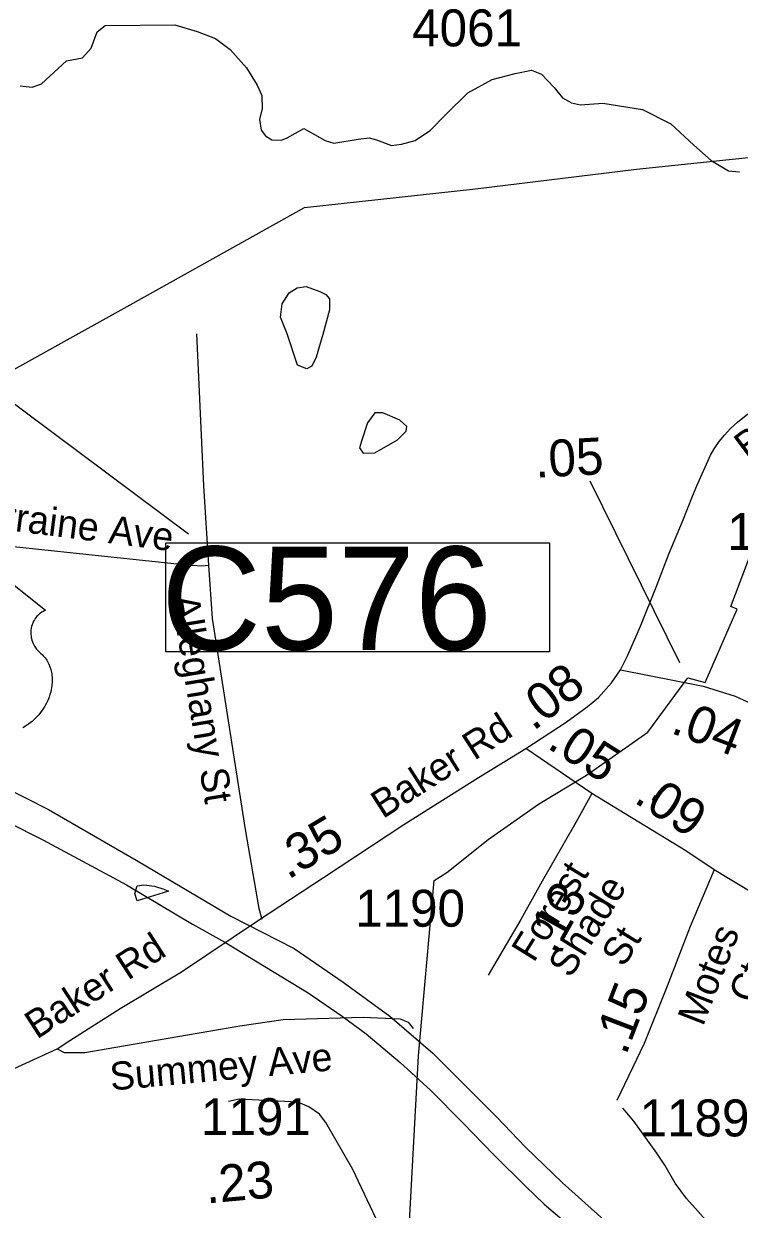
# Model space of a CAD drawing. Extents: x 1662474 to 1856135, y 779280 to 917889.
# Drawn here: x 1714222 to 1716644, y 797474 to 801486 of the extents above; entities that cross this region are included whole.
import ezdxf

# ---------------------------------------------------------------- set-up
doc = ezdxf.new("R2010")
doc.units = 0
for name, color, linetype in [('Exist Boundary Political City Limit New', 7, 'Continuous'), ('Exist Hydrographic Creek Single Shore', 7, 'Continuous'), ('Exist Hydrographic Misc Water Feature', 7, 'Continuous'), ('Exist Hydrographic Pond Under 1500 Sq Ft', 7, 'Continuous'), ('Exist Road Non-System Type 51', 7, 'Continuous'), ('Exist Road Non-System Type 51 Label', 7, 'Continuous'), ('Exist Road Primary Interstate Structure Culvert Number Label', 7, 'Continuous'), ('Exist Road Primary US Divided Attributed', 7, 'Continuous'), ('Exist Road Primary US Shield CELL', 7, 'Continuous'), ('Exist Road Secondary Mileage Hundredths English Label', 7, 'Continuous'), ('Exist Road Secondary Mileage Tenths English Label', 7, 'Continuous'), ('Exist Road Secondary Type 41 Attributed', 7, 'Continuous'), ('Exist Road Secondary Type 51 Attributed', 7, 'Continuous'), ('Exist Road Secondary Type 51 Label', 7, 'Continuous'), ('Exist Road Secondary Type 51 Number Label', 7, 'Continuous'), ('Exist Utilities Electrical Transmission Line', 7, 'Continuous'), ('Map Preparation Boundary City Limit Buffer Line', 7, 'Continuous'), ('Prop Road Primary US Projected', 7, 'Continuous')]:
    doc.layers.add(name, color=color, linetype=linetype)

msp = doc.modelspace()

# ---------------------------------------------------------------- linework, layer by layer
at = {"layer": 'Exist Boundary Political City Limit New'}
msp.add_lwpolyline([(1715477.8, 796498.7), (1715559, 797993.3), (1715611.1, 798586.8), (1715654.6, 798614.2), (1715793.8, 798724.9), (1715964.4, 798844.9), (1716127.2, 798943.5), (1716334.5, 799088.1), (1716469.9, 799272.8), (1716528.6, 799256.2), (1716637.1, 799505.2), (1716615.4, 799514.4), (1716691.5, 799713.8)], dxfattribs=at)
at = {"layer": 'Exist Hydrographic Creek Single Shore'}
msp.add_lwpolyline([(1714210.5, 801276.6), (1714251.1, 801271.9), (1714282.6, 801282.4), (1714367.4, 801361.1), (1714421.8, 801371.1), (1714451.1, 801403.1), (1714471.4, 801459), (1714498.4, 801480.5), (1714734.1, 801482.6), (1714809.4, 801460.1), (1714871.4, 801436.2), (1714921, 801398.9), (1714975.9, 801336.9), (1715012, 801278.2), (1715028.6, 801243.2), (1715029.6, 801199.4), (1715020.1, 801162.4), (1715026.5, 801126.4), (1715040.6, 801106.5), (1715061.6, 801093.1), (1715094.8, 801092.1), (1715114.4, 801100.5), (1715170, 801131.2), (1715242.5, 801091), (1715272.4, 801081.8), (1715353.8, 801095.5), (1715391.2, 801100.2), (1715416.8, 801093.1), (1715467.6, 801073.7), (1715500.8, 801078.7), (1715547.2, 801091), (1715598.9, 801126.2), (1715650.6, 801178.9), (1715725.1, 801252.4), (1715807.9, 801297.6), (1715886, 801318.3), (1715940.9, 801329.6), (1715975.2, 801315.2), (1716017.5, 801270), (1716046.4, 801235.9), (1716076, 801219.1), (1716107.2, 801212), (1716181.9, 801217), (1716316.2, 801195.5), (1716413, 801147.2), (1716490.5, 801074.8), (1716549.5, 801023.8), (1716607.2, 800988.7), (1716644.5, 800984.8)], dxfattribs=at)
at = {"layer": 'Exist Hydrographic Misc Water Feature'}
for points in [[(1714606, 798518.2), (1714598.4, 798542.2), (1714606.6, 798568.2), (1714628.6, 798572), (1714664.6, 798567.6), (1714696.5, 798557.3), (1714712.5, 798551.1), (1714694.3, 798545.3), (1714606, 798518.2)], [(1715933.2, 796479), (1715907.8, 796543.3), (1715884.4, 796615.5), (1715871.2, 796687.6), (1715859.8, 796757.8), (1715852.5, 796823.8), (1715847.1, 796887.9), (1715825.5, 796938.2), (1715789.8, 796974.4), (1715716.6, 797057.2), (1715671.2, 797123.6), (1715629.7, 797178.1), (1715582.2, 797224.5), (1715524.6, 797269.1), (1715487, 797317.4), (1715443.6, 797381.9), (1715365, 797546.6), (1715335.7, 797609), (1715245.2, 797767.8), (1715223.5, 797796.1), (1715187.7, 797820.5), (1715149.8, 797836.8), (1714951.9, 797846.7), (1714915.8, 797839)], [(1716675.7, 796508), (1716680.6, 796599.9), (1716687.6, 796709.9), (1716698.5, 796801.8), (1716709.9, 796949.7), (1716710.5, 797005.8), (1716709.3, 797087.8), (1716703.6, 797133.9), (1716682.3, 797208.2), (1716658.8, 797264.3), (1716631.3, 797310.6), (1716587.9, 797367), (1716548.2, 797417.5), (1716504.7, 797465.9), (1716465.1, 797510.3), (1716427.6, 797562.6), (1716392.3, 797623), (1716364.6, 797663.3), (1716287.6, 797772), (1716263.9, 797800.2), (1716250, 797816.3)]]:
    msp.add_lwpolyline(points, dxfattribs=at)
at = {"layer": 'Exist Hydrographic Pond Under 1500 Sq Ft'}
for points in [[(1715149.3, 800331), (1715114.1, 800436.7), (1715091.3, 800492.7), (1715097.5, 800538.3), (1715120.3, 800575.6), (1715147.3, 800592.2), (1715178.4, 800596.4), (1715224, 800579.8), (1715244.8, 800569.4), (1715257.2, 800554.9), (1715257.2, 800517.6), (1715234.4, 800434.7), (1715211.6, 800358), (1715197.1, 800326.9), (1715180.5, 800318.6), (1715149.3, 800331)], [(1715495.7, 800144.4), (1715437.7, 800169.3), (1715410.7, 800169.3), (1715385.8, 800136.1), (1715365.1, 800073.9), (1715358.8, 800051.1), (1715371.3, 800032.5), (1715410.7, 800034.5), (1715487.5, 800078.1), (1715516.5, 800107.1), (1715518.6, 800123.7), (1715495.7, 800144.4)]]:
    msp.add_lwpolyline(points, dxfattribs=at)
at = {"layer": 'Exist Road Non-System Type 51'}
for points in [[(1714807, 800436.7), (1714831.1, 799922.2), (1714847.4, 799654)], [(1713811.5, 799976.6), (1713823.1, 799811.5), (1713829.1, 799795), (1713863.2, 799761.7), (1713880.2, 799755.6), (1713920.4, 799745.1), (1714773.1, 799654.9), (1714824.9, 799651.2), (1714847.4, 799654)], [(1714847.4, 799654), (1714860.4, 799473.4), (1714971.9, 798759.2), (1715018.4, 798491.9), (1715027.8, 798455.9)]]:
    msp.add_lwpolyline(points, dxfattribs=at)
at = {"layer": 'Exist Road Primary Interstate Structure Culvert Number Label'}
msp.add_line((1712986.3, 801099.1), (1714779.6, 799760), dxfattribs=at)
msp.add_lwpolyline([(1714703.5, 799729.5), (1716001.4, 799729.5), (1716001.4, 799360.8), (1714703.5, 799360.8)], close=True, dxfattribs=at)
at = {"layer": 'Exist Road Primary US Divided Attributed'}
for points in [[(1713262.6, 799302.3), (1713434.8, 799182.2), (1713587.9, 799069.8), (1713692.3, 799024.8), (1713860.5, 798940.7), (1714051.7, 798842.9), (1714287.3, 798724.2)], [(1713436.3, 799306.8), (1713683.9, 799134.5), (1713997.7, 798983.1), (1714306.7, 798826.7)]]:
    msp.add_lwpolyline(points, dxfattribs=at)
at = {"layer": 'Exist Road Primary US Shield CELL'}
msp.add_lwpolyline([(1714190, 799585.9), (1714296.3, 799501.3), (1714293.8, 799500.3), (1714288, 799497.5), (1714283.4, 799494.8), (1714276.1, 799489.6), (1714273, 799486.8), (1714269.8, 799483.8), (1714266.9, 799480.7), (1714264.4, 799477.7), (1714261.3, 799473.5), (1714258.6, 799469.2), (1714255.9, 799464.5), (1714253.9, 799460.4), (1714250.6, 799451.9), (1714249, 799446.5), (1714248, 799441.9), (1714246.8, 799432.4), (1714246.5, 799427.9), (1714246.5, 799423.4), (1714246.7, 799418.7), (1714247.2, 799414.2), (1714248, 799409.5), (1714248.7, 799405.3), (1714250.1, 799400.3), (1714251.9, 799394.4), (1714254.3, 799388.6), (1714259.1, 799379.4), (1714265.4, 799370), (1714269.8, 799364.7), (1714274.2, 799360.2), (1714280.8, 799354.7), (1714284.3, 799351.5), (1714288.4, 799347.4), (1714295.1, 799339.7), (1714297.8, 799336.1), (1714300.5, 799332), (1714303, 799327.8), (1714305.5, 799323.3), (1714307.5, 799319.3), (1714311.2, 799310.2), (1714314, 799301.3), (1714315.2, 799296.7), (1714317.2, 799286.3), (1714318, 799281.1), (1714318.8, 799270.9), (1714318.8, 799258.6), (1714317.9, 799247), (1714315.7, 799233.3), (1714313.9, 799225.2), (1714311.1, 799215.7), (1714308.4, 799207.5), (1714303.5, 799195.3), (1714299.2, 799186.5), (1714293.6, 799176.3), (1714289.8, 799170), (1714285.3, 799163.4), (1714279.7, 799155.7), (1714273.2, 799147.6), (1714265.4, 799138.9), (1714259, 799132.6), (1714250.7, 799125.2), (1714245.7, 799121), (1714238.6, 799115.6), (1714228.8, 799109.1), (1714219.1, 799103.5)], dxfattribs=at)
at = {"layer": 'Exist Road Secondary Mileage Tenths English Label'}
msp.add_line((1716442.4, 799323.8), (1716139, 799938.6), dxfattribs=at)
at = {"layer": 'Exist Road Secondary Type 41 Attributed'}
msp.add_lwpolyline([(1716144.7, 798881.2), (1716090.7, 798783.4), (1715976.8, 798584.8), (1715904.3, 798454.8), (1715794.4, 798266.4)], dxfattribs=at)
at = {"layer": 'Exist Road Secondary Type 51 Attributed'}
for points in [[(1716241.6, 799300), (1716267.4, 799349.3), (1716309.9, 799447.9), (1716362.7, 799579.4), (1716406.6, 799694.7), (1716451.5, 799801.9), (1716485.8, 799887.6), (1716500.5, 799922.1), (1716547.1, 800026.5), (1716558.7, 800047.4), (1716576, 800071.9), (1716594.3, 800094), (1716614.2, 800116.4), (1716637.8, 800137.4), (1716673.6, 800166.5)], [(1715921.5, 799033.2), (1716058.2, 799122), (1716129.6, 799174), (1716167.9, 799206.5), (1716211.7, 799255.9), (1716241.6, 799300)], [(1716241.6, 799300), (1716521.7, 799244.9), (1716630.5, 799210), (1716696.7, 799179.6)], [(1714335.6, 798017.4), (1714378.8, 798045), (1714548.9, 798153.5), (1714756.1, 798277.8), (1715016.5, 798452.9), (1715236.9, 798597.3), (1715508.8, 798775.9), (1715761.3, 798935), (1715921.5, 799033.2)], [(1716144.7, 798881.2), (1715921.5, 799033.2)], [(1716559.3, 798622.9), (1716463.7, 798686.6), (1716144.7, 798881.2)], [(1716559.3, 798622.9), (1716477.6, 798431.2), (1716400, 798229.3), (1716322.3, 798035.2), (1716229.8, 797842)], [(1716695.2, 798539.9), (1716559.3, 798622.9)], [(1714335.6, 798017.4), (1714359.7, 798004.3), (1714429.3, 798004.3), (1714953.8, 798094.7), (1715101, 798116.2), (1715371.6, 798124.3), (1715496.6, 798118.2), (1715523.8, 798107.1), (1715540.9, 798086)], [(1711980.1, 792720.4), (1712057.3, 793192.1), (1712117.7, 793573.1), (1712168.9, 793949.6), (1712234, 794372.5), (1712271.2, 794651.3), (1712289.2, 794759), (1712329.2, 794912.6), (1712473.9, 795357.1), (1712559.9, 795520.4), (1712593.7, 795605.5), (1712625.8, 795705.1), (1712648.3, 795803), (1712674.7, 795925.5), (1712699.3, 796156.8), (1712781.9, 796663.3), (1712836.2, 796867.3), (1712887.2, 796972.5), (1712944.6, 797071.4), (1713225.3, 797396.5), (1713368.9, 797536.8), (1713589, 797689.8), (1713974.4, 797851.7), (1714335.6, 798017.4)]]:
    msp.add_lwpolyline(points, dxfattribs=at)
at = {"layer": 'Exist Utilities Electrical Transmission Line'}
msp.add_lwpolyline([(1711475, 799701.9), (1711785.1, 799697.6), (1712160.6, 799682.4), (1712618.5, 799666.2), (1713024.5, 799664.8), (1713393.1, 799871.3), (1714066.4, 800247.9), (1714582.3, 800534.5), (1715172.6, 800864.2), (1715751.6, 800927.9), (1716296.5, 800994.3), (1716760.9, 801042)], dxfattribs=at)
at = {"layer": 'Map Preparation Boundary City Limit Buffer Line'}
msp.add_lwpolyline([(1715477.8, 796498.7), (1715559, 797993.3), (1715611.1, 798586.8), (1715654.6, 798614.2), (1715793.8, 798724.9), (1715964.4, 798844.9), (1716127.2, 798943.5), (1716334.5, 799088.1), (1716469.9, 799272.8), (1716528.6, 799256.2), (1716637.1, 799505.2), (1716615.4, 799514.4), (1716691.5, 799713.8)], dxfattribs=at)
at = {"layer": 'Prop Road Primary US Projected'}
for points in [[(1714306.7, 798826.7), (1714610.5, 798651.1), (1714923.8, 798466), (1715137.4, 798356.8), (1715303.5, 798242.9), (1715461.6, 798127.8), (1715607, 798002.5), (1715822.4, 797787), (1715920.2, 797684.3), (1716045.5, 797564), (1716185.8, 797438.7), (1716283.5, 797368.6), (1716418.8, 797285.9), (1716554.1, 797213.2), (1716666.9, 797163.1)], [(1714287.3, 798724.2), (1714570.2, 798571.6), (1714793.2, 798438.6), (1714902.9, 798377.4)], [(1714902.9, 798377.4), (1715012.5, 798310.9), (1715185.2, 798206.6), (1715300.2, 798127.5), (1715381.2, 798068.2), (1715496.2, 797971.1), (1715600.5, 797875.8), (1715708.4, 797766.1), (1715812.9, 797658.2), (1715921.4, 797551.2), (1715984.1, 797491.6), (1716045.2, 797439.6), (1716104.8, 797387.7), (1716141.5, 797358.6), (1716236.3, 797291.4), (1716323.4, 797233.3), (1716422.7, 797176.8), (1716506.8, 797135.5), (1716624.4, 797075.9), (1716713.1, 797045.3)]]:
    msp.add_lwpolyline(points, dxfattribs=at)

# ---------------------------------------------------------------- texts
at = {"layer": 'Exist Road Non-System Type 51 Label'}
for s, rotation, p in [('Lorraine Ave', 352.7119, (1714008.5, 799792.5)), ('Alleghany St', 279.3332, (1714721.1, 799546.4))]:
    msp.add_text(s, height=95, rotation=rotation, dxfattribs=at).set_placement(p)
at = {"layer": 'Exist Road Primary Interstate Structure Culvert Number Label'}
msp.add_text('C576', height=350, dxfattribs=at).set_placement((1714687.5, 799366.9))
at = {"layer": 'Exist Road Secondary Mileage Hundredths English Label'}
for s, rotation, p in [('.05', 327.6712, (1715989.7, 799037.2)), ('.13', 60.8324, (1716020.4, 798331.9))]:
    msp.add_text(s, height=125, rotation=rotation, dxfattribs=at).set_placement(p)
at = {"layer": 'Exist Road Secondary Mileage Tenths English Label'}
for s, rotation, p in [('.05', 3.1157, (1715955.3, 799949.5)), ('.08', 37.899, (1715947.1, 799090.3)), ('.04 ', 339.316, (1716408.4, 799087.3)), ('.09', 327.2085, (1716283.5, 798853.5)), ('.', 330.6537, (1716334, 798866.5)), ('.35', 30.9026, (1715116.8, 798587.9)), ('.15', 68.9478, (1716260.5, 797992.2)), ('.23', 5.2466, (1714841.7, 797493.4))]:
    msp.add_text(s, height=125, rotation=rotation, dxfattribs=at).set_placement(p)
at = {"layer": 'Exist Road Secondary Type 51 Label'}
for s, rotation, p in [('Baker Rd', 36.8772, (1716673.2, 800005.5)), ('Baker Rd', 32.5651, (1715437.7, 798793.6)), ('Forest', 58.3132, (1715948.7, 798305.7)), (' Shade', 58.3132, (1716054.5, 798222.6)), ('Baker Rd', 32.8905, (1714266.4, 798047.6)), (' St', 58.3132, (1716234.4, 798259.5)), ('Motes', 68.7471, (1716521.2, 798090.2)), (' Ct', 68.7471, (1716681.3, 798132.9)), ('Summey Ave', 5.2135, (1714518.2, 797875.7))]:
    msp.add_text(s, height=95, rotation=rotation, dxfattribs=at).set_placement(p)
at = {"layer": 'Exist Road Secondary Type 51 Number Label'}
for s, p in [('4061', (1715536.9, 801409.7)), ('1248', (1716603.9, 799705.1)), ('1190', (1715344, 798430.3)), ('1191', (1714822.4, 797724.9)), ('1189', (1716306.8, 797720.6))]:
    msp.add_text(s, height=125, dxfattribs=at).set_placement(p)

doc.saveas('drawing.dxf')
